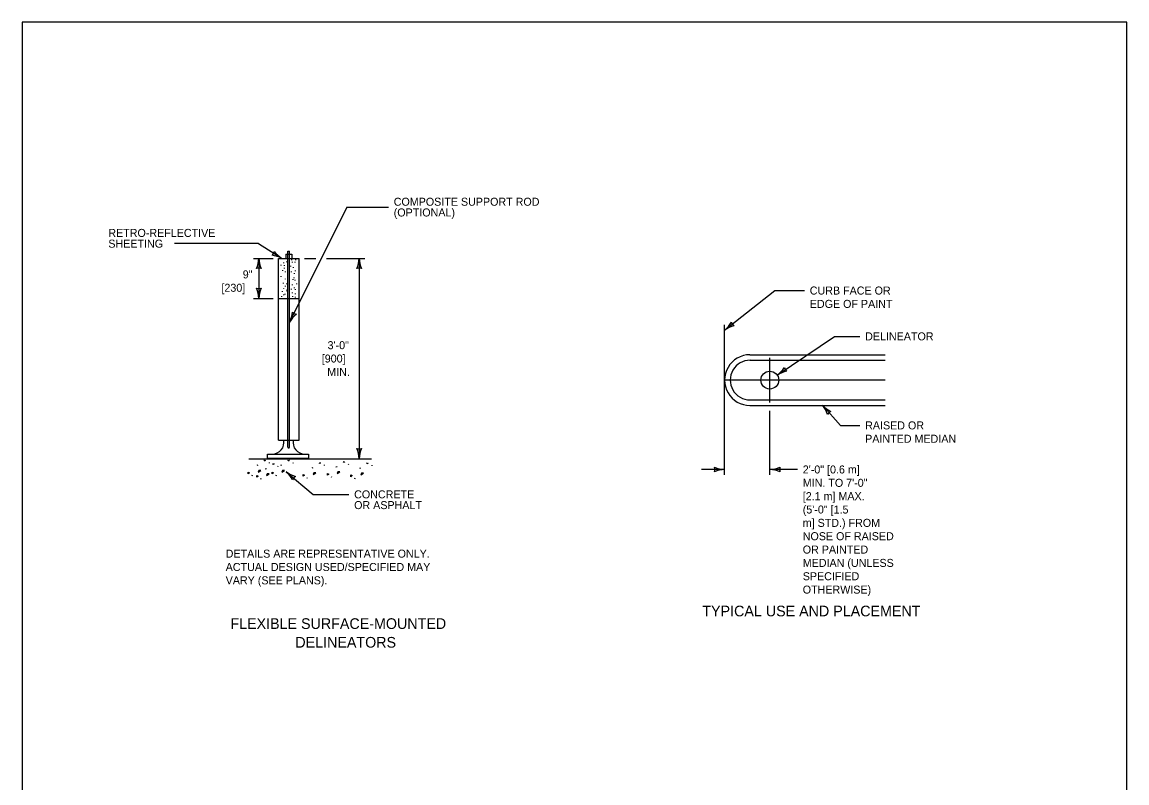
# Model space of a CAD drawing. Extents: x 49991.4 to 50021, y 49987.6 to 50011.4.
# Drawn here: x 50000.34 to 50008.61, y 50005.56 to 50011.26 of the extents above; entities that cross this region are included whole.
import ezdxf

# ---------------------------------------------------------------- set-up
doc = ezdxf.new("R2010")
doc.units = 0
for name, color, linetype in [('Level 1', 7, 'Continuous'), ('Level 2', 7, 'Continuous'), ('Level 3', 7, 'Continuous'), ('Level 4', 7, 'Continuous'), ('Level 5', 7, 'Continuous')]:
    doc.layers.add(name, color=color, linetype=linetype)

msp = doc.modelspace()

# ---------------------------------------------------------------- linework, layer by layer
at = {"layer": 'Level 1'}
for p, q in [((50002.2565, 50009.4924), (50002.4127, 50009.4924)), ((50002.2565, 50008.1298), (50002.2565, 50009.4924)), ((50002.2829, 50009.4862), (50002.2829, 50009.4911)), ((50002.3119, 50009.5234), (50002.3119, 50009.4926)), ((50002.3119, 50009.5234), (50002.3571, 50009.5234)), ((50002.3192, 50009.4646), (50002.3192, 50009.4694)), ((50002.328, 50009.5469), (50002.3402, 50009.5469)), ((50002.328, 50009.5234), (50002.328, 50009.5469)), ((50002.3402, 50009.5234), (50002.3402, 50009.5469)), ((50002.3571, 50009.5234), (50002.3571, 50009.4926)), ((50002.3575, 50009.4794), (50002.3575, 50009.4843)), ((50002.361, 50009.4624), (50002.361, 50009.4673)), ((50002.382, 50009.4611), (50002.382, 50009.4659)), ((50002.3867, 50009.4787), (50002.3867, 50009.4836)), ((50002.4127, 50008.1298), (50002.4127, 50009.4924)), ((50002.2762, 50009.4393), (50002.2762, 50009.4442)), ((50002.2884, 50009.4001), (50002.2884, 50009.4049)), ((50002.2965, 50009.4577), (50002.2965, 50009.4626)), ((50002.3016, 50009.4374), (50002.3016, 50009.4423)), ((50002.3016, 50009.4171), (50002.3016, 50009.4219)), ((50002.3097, 50009.3899), (50002.3097, 50009.3948)), ((50002.328, 50009.3906), (50002.328, 50009.3954)), ((50002.3484, 50009.4319), (50002.3484, 50009.4368)), ((50002.3541, 50009.3898), (50002.3541, 50009.3947)), ((50002.3705, 50009.4211), (50002.3705, 50009.4259)), ((50002.3772, 50009.3777), (50002.3772, 50009.3826)), ((50002.384, 50009.3959), (50002.384, 50009.4008)), ((50002.2782, 50009.3546), (50002.2782, 50009.3594)), ((50002.2951, 50009.3051), (50002.2951, 50009.3099)), ((50002.3097, 50009.3356), (50002.3097, 50009.3404)), ((50002.3185, 50009.2983), (50002.3185, 50009.3032)), ((50002.3677, 50009.3328), (50002.3677, 50009.3377)), ((50002.3739, 50009.3437), (50002.3739, 50009.3486)), ((50002.382, 50009.3261), (50002.382, 50009.3309)), ((50002.3949, 50009.3003), (50002.3949, 50009.3052)), ((50002.2864, 50009.2413), (50002.2864, 50009.2462)), ((50002.2959, 50009.2631), (50002.2959, 50009.2679)), ((50002.2961, 50009.2169), (50002.2961, 50009.2218)), ((50002.307, 50009.2231), (50002.307, 50009.2279)), ((50002.309, 50009.2821), (50002.309, 50009.2869)), ((50002.3192, 50009.2508), (50002.3192, 50009.2557)), ((50002.3232, 50009.2421), (50002.3232, 50009.2469)), ((50002.3541, 50009.2583), (50002.3541, 50009.2632)), ((50002.3616, 50009.2922), (50002.3616, 50009.2971)), ((50002.3622, 50009.2318), (50002.3622, 50009.2367)), ((50002.3772, 50009.2691), (50002.3772, 50009.2739)), ((50002.384, 50009.2562), (50002.384, 50009.2611)), ((50002.384, 50009.2243), (50002.384, 50009.2292)), ((50002.2565, 50009.1924), (50002.4127, 50009.1924)), ((50002.2829, 50009.2033), (50002.2829, 50009.2082)), ((50002.326, 50009.2033), (50002.326, 50009.2082)), ((50002.3644, 50009.2039), (50002.3644, 50009.2088)), ((50002.384, 50009.1992), (50002.384, 50009.2041)), ((50005.7899, 50008.7292), (50006.8028, 50008.7292)), ((50005.79, 50008.7705), (50006.8028, 50008.7705)), ((50005.79, 50008.3907), (50006.8028, 50008.3907)), ((50005.7903, 50008.4319), (50006.8028, 50008.4319)), ((50002.2565, 50008.1298), (50002.4127, 50008.1298)), ((50002.0343, 50007.9918), (50002.9541, 50007.9918)), ((50002.1508, 50007.9744), (50002.1541, 50007.9821)), ((50002.1581, 50007.9762), (50002.1508, 50007.9744)), ((50002.1541, 50007.9821), (50002.1581, 50007.9762)), ((50002.3297, 50007.9744), (50002.333, 50007.9821)), ((50002.337, 50007.9762), (50002.3297, 50007.9744)), ((50002.333, 50007.9821), (50002.337, 50007.9762)), ((50002.1015, 50007.942), (50002.0938, 50007.9395)), ((50002.1089, 50007.9042), (50002.1038, 50007.8913)), ((50002.1038, 50007.8913), (50002.1236, 50007.9038)), ((50002.1236, 50007.9038), (50002.1089, 50007.9042)), ((50002.1659, 50007.9169), (50002.1582, 50007.9144)), ((50002.1886, 50007.9586), (50002.1893, 50007.9644)), ((50002.2152, 50007.9493), (50002.2185, 50007.957)), ((50002.2225, 50007.9511), (50002.2152, 50007.9493)), ((50002.2185, 50007.957), (50002.2225, 50007.9511)), ((50002.253, 50007.9335), (50002.2537, 50007.9393)), ((50002.2804, 50007.942), (50002.2727, 50007.9395)), ((50002.2878, 50007.9042), (50002.2827, 50007.8913)), ((50002.2827, 50007.8913), (50002.3025, 50007.9038)), ((50002.3025, 50007.9038), (50002.2878, 50007.9042)), ((50002.3675, 50007.9586), (50002.3682, 50007.9644)), ((50002.5139, 50007.9236), (50002.5062, 50007.9211)), ((50002.5632, 50007.956), (50002.5665, 50007.9637)), ((50002.5705, 50007.9578), (50002.5632, 50007.956)), ((50002.5665, 50007.9637), (50002.5705, 50007.9578)), ((50002.601, 50007.9402), (50002.6017, 50007.946)), ((50002.6954, 50007.9312), (50002.6877, 50007.9287)), ((50002.7028, 50007.8934), (50002.6977, 50007.8805)), ((50002.6977, 50007.8805), (50002.7175, 50007.893)), ((50002.7175, 50007.893), (50002.7028, 50007.8934)), ((50002.7447, 50007.9636), (50002.748, 50007.9713)), ((50002.752, 50007.9654), (50002.7447, 50007.9636)), ((50002.748, 50007.9713), (50002.752, 50007.9654)), ((50002.7825, 50007.9478), (50002.7832, 50007.9536)), ((50002.8707, 50007.9205), (50002.863, 50007.918)), ((50002.92, 50007.9529), (50002.9233, 50007.9606)), ((50002.9273, 50007.9547), (50002.92, 50007.9529)), ((50002.9233, 50007.9606), (50002.9273, 50007.9547)), ((50002.9578, 50007.9371), (50002.9585, 50007.9429)), ((50002.0295, 50007.8781), (50002.0303, 50007.8917)), ((50002.0398, 50007.8862), (50002.0295, 50007.8781)), ((50002.0303, 50007.8917), (50002.0398, 50007.8862)), ((50002.0604, 50007.8678), (50002.0578, 50007.8609)), ((50002.0939, 50007.853), (50002.0947, 50007.8666)), ((50002.1042, 50007.8611), (50002.0939, 50007.853)), ((50002.0947, 50007.8666), (50002.1042, 50007.8611)), ((50002.1248, 50007.8427), (50002.1222, 50007.8358)), ((50002.1733, 50007.8791), (50002.1682, 50007.8662)), ((50002.1682, 50007.8662), (50002.188, 50007.8787)), ((50002.188, 50007.8787), (50002.1733, 50007.8791)), ((50002.2084, 50007.8781), (50002.2092, 50007.8917)), ((50002.2187, 50007.8862), (50002.2084, 50007.8781)), ((50002.2092, 50007.8917), (50002.2187, 50007.8862)), ((50002.2393, 50007.8678), (50002.2367, 50007.8609)), ((50002.4419, 50007.8597), (50002.4427, 50007.8733)), ((50002.4522, 50007.8678), (50002.4419, 50007.8597)), ((50002.4427, 50007.8733), (50002.4522, 50007.8678)), ((50002.4728, 50007.8494), (50002.4702, 50007.8425)), ((50002.5213, 50007.8858), (50002.5162, 50007.8729)), ((50002.5162, 50007.8729), (50002.536, 50007.8854)), ((50002.536, 50007.8854), (50002.5213, 50007.8858)), ((50002.6234, 50007.8673), (50002.6242, 50007.8809)), ((50002.6337, 50007.8754), (50002.6234, 50007.8673)), ((50002.6242, 50007.8809), (50002.6337, 50007.8754)), ((50002.6543, 50007.857), (50002.6517, 50007.8501)), ((50002.7987, 50007.8566), (50002.7995, 50007.8702)), ((50002.809, 50007.8647), (50002.7987, 50007.8566)), ((50002.7995, 50007.8702), (50002.809, 50007.8647)), ((50002.8296, 50007.8463), (50002.827, 50007.8394)), ((50002.8781, 50007.8827), (50002.873, 50007.8698)), ((50002.873, 50007.8698), (50002.8928, 50007.8823)), ((50002.8928, 50007.8823), (50002.8781, 50007.8827))]:
    msp.add_line(p, q, dxfattribs=at)
for points in [[(50008.6146, 50011.2628), (50000.3356, 50011.2628), (50000.3356, 50000.0624), (50008.6146, 50000.0624)], [(50002.4828, 50008.0266), (50002.4828, 50007.992), (50002.1753, 50007.992), (50002.1753, 50008.0266)]]:
    msp.add_lwpolyline(points, close=True, dxfattribs=at)
msp.add_circle((50005.9385, 50008.5806), 0.0669, dxfattribs=at)
for centre, radius, start, end in [((50005.79, 50008.5806), 0.1899, 90, 270.01378), ((50005.7905, 50008.5806), 0.1486, 89.78101, 269.91845), ((50002.2111, 50008.1132), 0.0866, 270.11677, 11.05539), ((50002.4528, 50008.1132), 0.0866, 168.94461, 269.88323)]:
    msp.add_arc(centre, radius, start, end, dxfattribs=at)
at = {"layer": 'Level 3'}
for p, q in [((50002.7693, 50009.8767), (50002.3403, 50009.0155)), ((50002.7693, 50009.8767), (50003.0804, 50009.8767)), ((50002.1083, 50009.6028), (50001.4767, 50009.6028)), ((50002.1083, 50009.6028), (50002.2773, 50009.496)), ((50002.0698, 50009.4924), (50002.2165, 50009.4924)), ((50002.1098, 50009.4924), (50002.1098, 50009.1924)), ((50002.4527, 50009.4924), (50002.5379, 50009.4924)), ((50002.6179, 50009.4924), (50002.9047, 50009.4924)), ((50002.8617, 50009.4924), (50002.8617, 50007.9918)), ((50002.0698, 50009.1924), (50002.2165, 50009.1924)), ((50005.6001, 50007.8709), (50005.6001, 50008.9945)), ((50005.9385, 50007.8709), (50005.9385, 50008.3507)), ((50002.3146, 50007.8942), (50002.5166, 50007.7244)), ((50005.6001, 50007.9109), (50005.4266, 50007.9109)), ((50006.1455, 50007.9109), (50005.9385, 50007.9109)), ((50002.5166, 50007.7244), (50002.7838, 50007.7244))]:
    msp.add_line(p, q, dxfattribs=at)
for points in [[(50005.6001, 50008.9545), (50005.9754, 50009.2515), (50006.1982, 50009.2515)], [(50005.9939, 50008.618), (50006.4246, 50008.9082), (50006.613, 50008.9082)], [(50006.336, 50008.3907), (50006.4689, 50008.2411), (50006.613, 50008.2411)]]:
    msp.add_lwpolyline(points, dxfattribs=at)
for centre, radius, start, end in [((50001.8877, 50009.5016), 0.2223, 337.45601, 357.63952), ((50002.3425, 50009.5039), 0.233, 182.82731, 202.07716), ((50002.1717, 50009.5562), 0.0548, 312.30837, 348.03073), ((50002.1771, 50009.2848), 0.233, 62.99686, 82.24671), ((50002.4014, 50009.6806), 0.2223, 217.62556, 237.80907), ((50002.6396, 50009.5016), 0.2223, 337.45601, 357.63952), ((50003.0944, 50009.5039), 0.233, 182.82731, 202.07716), ((50002.1098, 50009.3642), 0.0548, 72.13882, 107.86118), ((50002.8617, 50009.3642), 0.0548, 72.13882, 107.86118), ((50002.1098, 50009.3206), 0.0548, 252.13882, 287.86118), ((50001.8771, 50009.1809), 0.233, 2.82731, 22.07716), ((50002.3319, 50009.1833), 0.2223, 157.45601, 177.63952), ((50002.1292, 50009.1141), 0.233, 334.97095, 354.2208), ((50002.5324, 50008.9036), 0.2223, 129.59965, 149.78316), ((50002.4002, 50009.1289), 0.0548, 224.28246, 260.00482), ((50005.4511, 50009.1337), 0.233, 309.74126, 328.99111), ((50005.7262, 50008.7714), 0.2223, 104.36996, 124.55347), ((50005.7026, 50009.0315), 0.0548, 199.05277, 234.77513), ((50005.8543, 50008.8045), 0.233, 306.80474, 326.05459), ((50006.1105, 50008.4287), 0.2223, 101.43344, 121.61695), ((50006.1003, 50008.6896), 0.0548, 196.11625, 231.83861), ((50006.1598, 50008.2547), 0.2223, 18.02346, 38.20697), ((50006.5038, 50008.5523), 0.233, 223.39476, 242.64461), ((50006.4179, 50008.2948), 0.0548, 112.70627, 148.42863), ((50002.8617, 50008.12), 0.0548, 252.13882, 287.86118), ((50002.629, 50007.9803), 0.233, 2.82731, 22.07716), ((50003.0839, 50007.9827), 0.2223, 157.45601, 177.63952), ((50002.1667, 50007.7282), 0.2223, 28.11129, 48.2948), ((50002.4533, 50008.0815), 0.233, 233.48259, 252.73244), ((50005.6092, 50008.1331), 0.2223, 247.45601, 267.63952), ((50005.4719, 50007.9109), 0.0548, 342.13882, 17.86118), ((50005.6116, 50007.6782), 0.233, 92.82731, 112.07716), ((50005.927, 50008.1436), 0.233, 272.82731, 292.07716), ((50005.9293, 50007.6888), 0.2223, 67.45601, 87.63952), ((50006.0667, 50007.9109), 0.0548, 162.13882, 197.86118), ((50002.4138, 50007.8129), 0.0548, 122.7941, 158.51646)]:
    msp.add_arc(centre, radius, start, end, dxfattribs=at)
at = {"layer": 'Level 4'}
for p, q in [((50002.3281, 50008.0769), (50002.328, 50009.5234)), ((50002.3404, 50008.0769), (50002.3402, 50009.5234))]:
    msp.add_line(p, q, dxfattribs=at)
msp.add_arc((50002.3342, 50008.0782), 0.00625, 191.3719, 348.63732, dxfattribs=at)
at = {"layer": 'Level 5'}
for p, q in [((50005.9385, 50008.4138), (50005.9385, 50008.7475)), ((50006.8028, 50008.5806), (50005.6001, 50008.5806))]:
    msp.add_line(p, q, dxfattribs=at)

# ---------------------------------------------------------------- texts
at = {"layer": 'Level 2'}
for s, height, p in [('COMPOSITE SUPPORT ROD ', 0.06, (50003.1204, 50009.8869)), ('(OPTIONAL)', 0.06, (50003.1204, 50009.8065)), ('RETRO-REFLECTIVE ', 0.06, (50000.9818, 50009.6532)), ('SHEETING', 0.06, (50000.9818, 50009.5728)), ('9"', 0.06, (50001.9891, 50009.3424)), ('[230]', 0.06, (50001.8294, 50009.2424)), ('CURB FACE OR', 0.06, (50006.2382, 50009.2215)), ('EDGE OF PAINT', 0.06, (50006.2382, 50009.1215)), ('DELINEATOR', 0.06, (50006.653, 50008.8782)), ('3\'-0"', 0.06, (50002.6248, 50008.8121)), ('[900]', 0.06, (50002.5813, 50008.7121)), (' MIN.', 0.06, (50002.6001, 50008.6121)), ('RAISED OR', 0.06, (50006.653, 50008.2111)), ('PAINTED MEDIAN', 0.06, (50006.653, 50008.1111)), ('2\'-0" [0.6 m] ', 0.06, (50006.1855, 50007.8809)), ('MIN. TO 7\'-0"', 0.06, (50006.1855, 50007.7809)), ('CONCRETE ', 0.06, (50002.8238, 50007.6944)), ('[2.1 m] MAX.', 0.06, (50006.1855, 50007.6809)), ('OR ASPHALT', 0.06, (50002.8238, 50007.614)), ('(5\'-0" [1.5', 0.06, (50006.1855, 50007.5809)), ('m] STD.) FROM', 0.06, (50006.1855, 50007.4809)), ('NOSE OF RAISED', 0.06, (50006.1855, 50007.3809)), ('OR PAINTED ', 0.06, (50006.1855, 50007.2809)), ('DETAILS ARE REPRESENTATIVE ONLY.', 0.06, (50001.8611, 50007.2503)), ('MEDIAN (UNLESS', 0.06, (50006.1855, 50007.1809)), ('ACTUAL DESIGN USED/SPECIFIED MAY', 0.06, (50001.8611, 50007.1503)), ('VARY (SEE PLANS).', 0.06, (50001.8611, 50007.0503)), ('SPECIFIED ', 0.06, (50006.1855, 50007.0809)), ('OTHERWISE) ', 0.06, (50006.1855, 50006.9809)), ('TYPICAL USE AND PLACEMENT', 0.08, (50005.433, 50006.8105)), ('FLEXIBLE SURFACE-MOUNTED', 0.08, (50001.8967, 50006.7161)), ('DELINEATORS', 0.08, (50002.3831, 50006.5761))]:
    msp.add_text(s, height=height, dxfattribs=at).set_placement(p)

doc.saveas('drawing.dxf')
